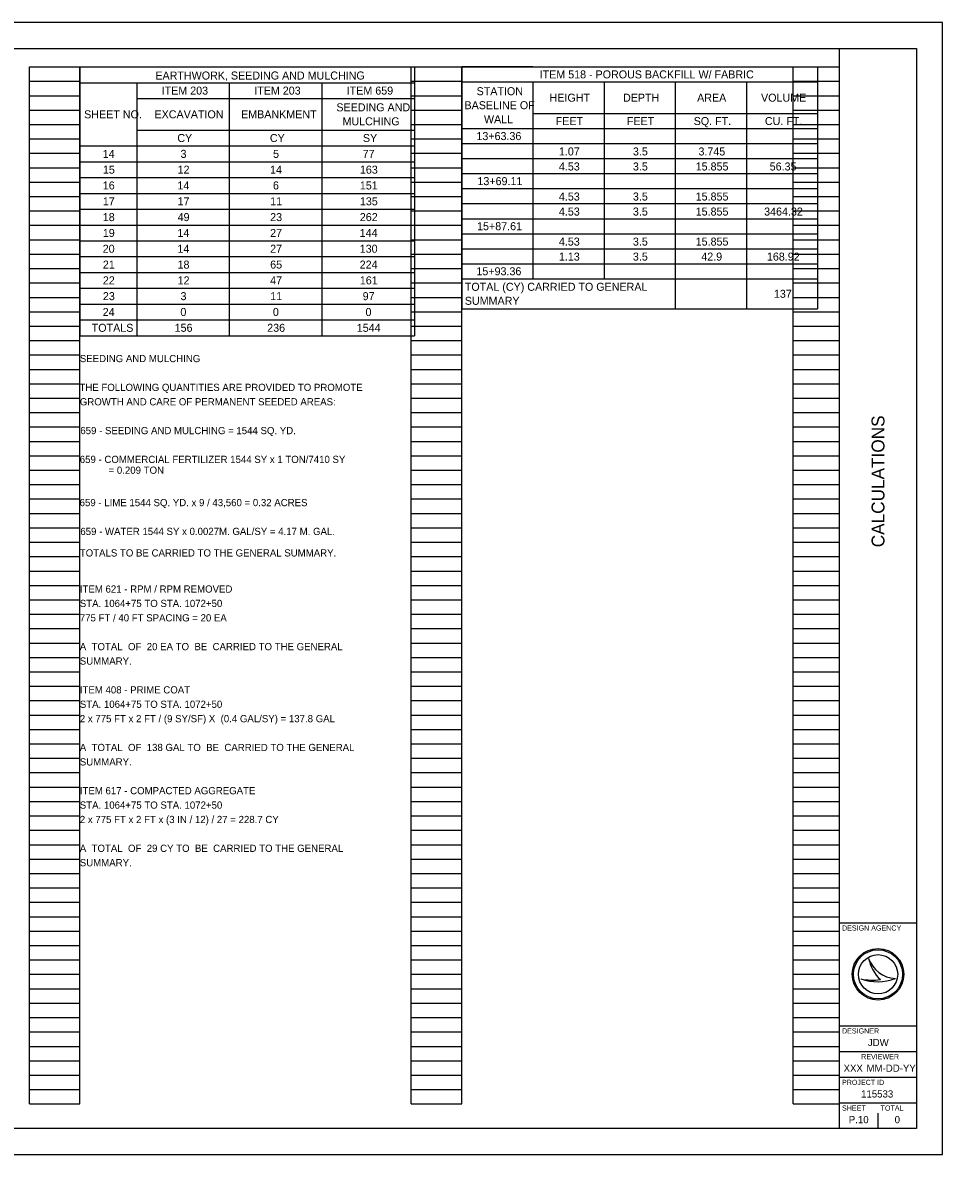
# Model space of a CAD drawing. Extents: x 0 to 34, y 0 to 22.
# Drawn here: x 16.13 to 34, y 0 to 22 of the extents above; entities that cross this region are included whole.
import ezdxf

# ---------------------------------------------------------------- set-up
doc = ezdxf.new("R2010")
doc.units = 0
for name, color, linetype in [('SH_Border', 7, 'Continuous'), ('SH_Cut_Line', 7, 'Continuous'), ('SH_Data', 7, 'Continuous'), ('SH_Text', 7, 'Continuous')]:
    doc.layers.add(name, color=color, linetype=linetype)

msp = doc.modelspace()

# ---------------------------------------------------------------- linework, layer by layer
at = {"layer": 'SH_Border'}
for p, q in [((32, 0.5), (32, 21.5)), ((32, 4.5), (33.5, 4.5)), ((32, 2.5), (33.5, 2.5)), ((32, 2), (33.5, 2)), ((32, 1.5), (33.5, 1.5)), ((32, 1), (33.5, 1))]:
    msp.add_line(p, q, dxfattribs=at)
msp.add_lwpolyline([(1.5, 21.5), (33.5, 21.5), (33.5, 0.5), (1.5, 0.5)], close=True, dxfattribs=at)
at = {"layer": 'SH_Cut_Line'}
msp.add_lwpolyline([(0, 0), (34, 0), (34, 22), (0, 22)], close=True, dxfattribs=at)
at = {"layer": 'SH_Data'}
for p, q in [((16.26, 0.98), (16.26, 21.14)), ((16.26, 21.14), (17.24, 21.14)), ((17.24, 0.98), (17.24, 21.14)), ((23.68, 0.98), (23.68, 21.14)), ((23.68, 21.14), (24.66, 21.14)), ((24.66, 0.98), (24.66, 21.14)), ((31.1, 0.98), (31.1, 21.14)), ((31.1, 21.14), (32, 21.14)), ((32, 0.98), (32, 21.14)), ((16.26, 20.86), (17.24, 20.86)), ((23.68, 20.86), (24.66, 20.86)), ((31.1, 20.86), (32, 20.86)), ((16.26, 20.58), (17.24, 20.58)), ((23.68, 20.58), (24.66, 20.58)), ((31.1, 20.58), (32, 20.58)), ((16.26, 20.3), (17.24, 20.3)), ((23.68, 20.3), (24.66, 20.3)), ((31.1, 20.3), (32, 20.3)), ((16.26, 20.02), (17.24, 20.02)), ((23.68, 20.02), (24.66, 20.02)), ((31.1, 20.02), (32, 20.02)), ((16.26, 19.74), (17.24, 19.74)), ((23.68, 19.74), (24.66, 19.74)), ((31.1, 19.74), (32, 19.74)), ((16.26, 19.46), (17.24, 19.46)), ((23.68, 19.46), (24.66, 19.46)), ((31.1, 19.46), (32, 19.46)), ((16.26, 19.18), (17.24, 19.18)), ((23.68, 19.18), (24.66, 19.18)), ((31.1, 19.18), (32, 19.18)), ((16.26, 18.9), (17.24, 18.9)), ((23.68, 18.9), (24.66, 18.9)), ((31.1, 18.9), (32, 18.9)), ((16.26, 18.62), (17.24, 18.62)), ((23.68, 18.62), (24.66, 18.62)), ((31.1, 18.62), (32, 18.62)), ((16.26, 18.34), (17.24, 18.34)), ((23.68, 18.34), (24.66, 18.34)), ((31.1, 18.34), (32, 18.34)), ((16.26, 18.06), (17.24, 18.06)), ((23.68, 18.06), (24.66, 18.06)), ((31.1, 18.06), (32, 18.06)), ((16.26, 17.78), (17.24, 17.78)), ((23.68, 17.78), (24.66, 17.78)), ((31.1, 17.78), (32, 17.78)), ((16.26, 17.5), (17.24, 17.5)), ((23.68, 17.5), (24.66, 17.5)), ((31.1, 17.5), (32, 17.5)), ((16.26, 17.22), (17.24, 17.22)), ((23.68, 17.22), (24.66, 17.22)), ((31.1, 17.22), (32, 17.22)), ((16.26, 16.94), (17.24, 16.94)), ((23.68, 16.94), (24.66, 16.94)), ((31.1, 16.94), (32, 16.94)), ((16.26, 16.66), (17.24, 16.66)), ((23.68, 16.66), (24.66, 16.66)), ((31.1, 16.66), (32, 16.66)), ((16.26, 16.38), (17.24, 16.38)), ((23.68, 16.38), (24.66, 16.38)), ((31.1, 16.38), (32, 16.38)), ((16.26, 16.1), (17.24, 16.1)), ((23.68, 16.1), (24.66, 16.1)), ((31.1, 16.1), (32, 16.1)), ((16.26, 15.82), (17.24, 15.82)), ((23.68, 15.82), (24.66, 15.82)), ((31.1, 15.82), (32, 15.82)), ((16.26, 15.54), (17.24, 15.54)), ((23.68, 15.54), (24.66, 15.54)), ((31.1, 15.54), (32, 15.54)), ((16.26, 15.26), (17.24, 15.26)), ((23.68, 15.26), (24.66, 15.26)), ((31.1, 15.26), (32, 15.26)), ((16.26, 14.98), (17.24, 14.98)), ((23.68, 14.98), (24.66, 14.98)), ((31.1, 14.98), (32, 14.98)), ((16.26, 14.7), (17.24, 14.7)), ((23.68, 14.7), (24.66, 14.7)), ((31.1, 14.7), (32, 14.7)), ((16.26, 14.42), (17.24, 14.42)), ((23.68, 14.42), (24.66, 14.42)), ((31.1, 14.42), (32, 14.42)), ((16.26, 14.14), (17.24, 14.14)), ((23.68, 14.14), (24.66, 14.14)), ((31.1, 14.14), (32, 14.14)), ((16.26, 13.86), (17.24, 13.86)), ((23.68, 13.86), (24.66, 13.86)), ((31.1, 13.86), (32, 13.86)), ((16.26, 13.58), (17.24, 13.58)), ((23.68, 13.58), (24.66, 13.58)), ((31.1, 13.58), (32, 13.58)), ((16.26, 13.3), (17.24, 13.3)), ((23.68, 13.3), (24.66, 13.3)), ((31.1, 13.3), (32, 13.3)), ((16.26, 13.02), (17.24, 13.02)), ((23.68, 13.02), (24.66, 13.02)), ((31.1, 13.02), (32, 13.02)), ((16.26, 12.74), (17.24, 12.74)), ((23.68, 12.74), (24.66, 12.74)), ((31.1, 12.74), (32, 12.74)), ((16.26, 12.46), (17.24, 12.46)), ((23.68, 12.46), (24.66, 12.46)), ((31.1, 12.46), (32, 12.46)), ((16.26, 12.18), (17.24, 12.18)), ((23.68, 12.18), (24.66, 12.18)), ((31.1, 12.18), (32, 12.18)), ((16.26, 11.9), (17.24, 11.9)), ((23.68, 11.9), (24.66, 11.9)), ((31.1, 11.9), (32, 11.9)), ((16.26, 11.62), (17.24, 11.62)), ((23.68, 11.62), (24.66, 11.62)), ((31.1, 11.62), (32, 11.62)), ((16.26, 11.34), (17.24, 11.34)), ((23.68, 11.34), (24.66, 11.34)), ((31.1, 11.34), (32, 11.34)), ((16.26, 11.06), (17.24, 11.06)), ((23.68, 11.06), (24.66, 11.06)), ((31.1, 11.06), (32, 11.06)), ((16.26, 10.78), (17.24, 10.78)), ((23.68, 10.78), (24.66, 10.78)), ((31.1, 10.78), (32, 10.78)), ((16.26, 10.5), (17.24, 10.5)), ((23.68, 10.5), (24.66, 10.5)), ((31.1, 10.5), (32, 10.5)), ((16.26, 10.22), (17.24, 10.22)), ((23.68, 10.22), (24.66, 10.22)), ((31.1, 10.22), (32, 10.22)), ((16.26, 9.94), (17.24, 9.94)), ((23.68, 9.94), (24.66, 9.94)), ((31.1, 9.94), (32, 9.94)), ((16.26, 9.66), (17.24, 9.66)), ((23.68, 9.66), (24.66, 9.66)), ((31.1, 9.66), (32, 9.66)), ((16.26, 9.38), (17.24, 9.38)), ((23.68, 9.38), (24.66, 9.38)), ((31.1, 9.38), (32, 9.38)), ((16.26, 9.1), (17.24, 9.1)), ((23.68, 9.1), (24.66, 9.1)), ((31.1, 9.1), (32, 9.1)), ((16.26, 8.82), (17.24, 8.82)), ((23.68, 8.82), (24.66, 8.82)), ((31.1, 8.82), (32, 8.82)), ((16.26, 8.54), (17.24, 8.54)), ((23.68, 8.54), (24.66, 8.54)), ((31.1, 8.54), (32, 8.54)), ((16.26, 8.26), (17.24, 8.26)), ((23.68, 8.26), (24.66, 8.26)), ((31.1, 8.26), (32, 8.26)), ((16.26, 7.98), (17.24, 7.98)), ((23.68, 7.98), (24.66, 7.98)), ((31.1, 7.98), (32, 7.98)), ((16.26, 7.7), (17.24, 7.7)), ((23.68, 7.7), (24.66, 7.7)), ((31.1, 7.7), (32, 7.7)), ((16.26, 7.42), (17.24, 7.42)), ((23.68, 7.42), (24.66, 7.42)), ((31.1, 7.42), (32, 7.42)), ((16.26, 7.14), (17.24, 7.14)), ((23.68, 7.14), (24.66, 7.14)), ((31.1, 7.14), (32, 7.14)), ((16.26, 6.86), (17.24, 6.86)), ((23.68, 6.86), (24.66, 6.86)), ((31.1, 6.86), (32, 6.86)), ((16.26, 6.58), (17.24, 6.58)), ((23.68, 6.58), (24.66, 6.58)), ((31.1, 6.58), (32, 6.58)), ((16.26, 6.3), (17.24, 6.3)), ((23.68, 6.3), (24.66, 6.3)), ((31.1, 6.3), (32, 6.3)), ((16.26, 6.02), (17.24, 6.02)), ((23.68, 6.02), (24.66, 6.02)), ((31.1, 6.02), (32, 6.02)), ((16.26, 5.74), (17.24, 5.74)), ((23.68, 5.74), (24.66, 5.74)), ((31.1, 5.74), (32, 5.74)), ((16.26, 5.46), (17.24, 5.46)), ((23.68, 5.46), (24.66, 5.46)), ((31.1, 5.46), (32, 5.46)), ((16.26, 5.18), (17.24, 5.18)), ((23.68, 5.18), (24.66, 5.18)), ((31.1, 5.18), (32, 5.18)), ((16.26, 4.9), (17.24, 4.9)), ((23.68, 4.9), (24.66, 4.9)), ((31.1, 4.9), (32, 4.9)), ((16.26, 4.62), (17.24, 4.62)), ((23.68, 4.62), (24.66, 4.62)), ((31.1, 4.62), (32, 4.62)), ((16.26, 4.34), (17.24, 4.34)), ((23.68, 4.34), (24.66, 4.34)), ((31.1, 4.34), (32, 4.34)), ((16.26, 4.06), (17.24, 4.06)), ((23.68, 4.06), (24.66, 4.06)), ((31.1, 4.06), (32, 4.06)), ((16.26, 3.78), (17.24, 3.78)), ((23.68, 3.78), (24.66, 3.78)), ((31.1, 3.78), (32, 3.78)), ((32.567, 3.81), (32.567, 3.81)), ((16.26, 3.5), (17.24, 3.5)), ((23.68, 3.5), (24.66, 3.5)), ((31.1, 3.5), (32, 3.5)), ((32.417, 3.41), (32.417, 3.41)), ((32.75, 3.5), (32.75, 3.5)), ((33.087, 3.419), (33.087, 3.419)), ((16.26, 3.22), (17.24, 3.22)), ((23.68, 3.22), (24.66, 3.22)), ((31.1, 3.22), (32, 3.22)), ((16.26, 2.94), (17.24, 2.94)), ((23.68, 2.94), (24.66, 2.94)), ((31.1, 2.94), (32, 2.94)), ((16.26, 2.66), (17.24, 2.66)), ((23.68, 2.66), (24.66, 2.66)), ((31.1, 2.66), (32, 2.66)), ((16.26, 2.38), (17.24, 2.38)), ((23.68, 2.38), (24.66, 2.38)), ((31.1, 2.38), (32, 2.38)), ((16.26, 2.1), (17.24, 2.1)), ((23.68, 2.1), (24.66, 2.1)), ((31.1, 2.1), (32, 2.1)), ((16.26, 1.82), (17.24, 1.82)), ((23.68, 1.82), (24.66, 1.82)), ((31.1, 1.82), (32, 1.82)), ((16.26, 1.54), (17.24, 1.54)), ((23.68, 1.54), (24.66, 1.54)), ((31.1, 1.54), (32, 1.54)), ((16.26, 1.26), (17.24, 1.26)), ((23.68, 1.26), (24.66, 1.26)), ((31.1, 1.26), (32, 1.26)), ((16.26, 0.98), (17.24, 0.98)), ((23.68, 0.98), (24.66, 0.98)), ((31.1, 0.98), (32, 0.98)), ((32.375, 0.675), (32.375, 0.675)), ((32.75, 0.5), (32.75, 0.8))]:
    msp.add_line(p, q, dxfattribs=at)
for radius in [0.5, 0.477, 0.477, 0.382]:
    msp.add_circle((32.75, 3.5), radius, dxfattribs=at)
for centre, radius, start, end in [((33.116, 3.998), 0.58, 198.9257, 198.9319), ((33.347, 3.97), 0.796, 191.6379, 191.6421), ((33.116, 3.998), 0.58, 198.9319, 267.1657), ((33.347, 3.97), 0.796, 191.6421, 226.0947), ((32.739, 4.37), 1.013, 251.4576, 290.0832), ((32.648, 4.654), 1.266, 259.4964, 259.4995), ((32.739, 4.37), 1.013, 251.4527, 251.4576), ((32.648, 4.654), 1.266, 259.4995, 276.6672)]:
    msp.add_arc(centre, radius, start, end, dxfattribs=at)
at = {"layer": 'SH_Text'}
for p, q in [((17.24, 21.14), (23.742, 21.14)), ((17.24, 21.14), (17.24, 15.914)), ((23.742, 21.14), (23.742, 15.914)), ((24.66, 21.14), (31.577, 21.14)), ((24.66, 21.14), (24.66, 16.436)), ((31.577, 21.14), (31.577, 16.436)), ((17.24, 20.833), (23.742, 20.833)), ((18.347, 20.833), (18.347, 15.914)), ((20.145, 20.833), (20.145, 15.914)), ((21.944, 20.833), (21.944, 15.914)), ((24.66, 20.848), (31.577, 20.848)), ((26.043, 20.848), (26.043, 17.021)), ((27.427, 20.848), (27.427, 17.021)), ((28.81, 20.848), (28.81, 16.436)), ((30.194, 20.848), (30.194, 16.436)), ((18.347, 20.525), (23.742, 20.525)), ((26.043, 20.233), (31.577, 20.233)), ((18.347, 19.91), (23.742, 19.91)), ((24.66, 19.941), (31.577, 19.941)), ((17.24, 19.603), (23.742, 19.603)), ((24.66, 19.649), (31.577, 19.649)), ((17.24, 19.295), (23.742, 19.295)), ((24.66, 19.357), (31.577, 19.357)), ((17.24, 18.988), (23.742, 18.988)), ((24.66, 19.065), (31.577, 19.065)), ((24.66, 18.773), (31.577, 18.773)), ((17.24, 18.681), (23.742, 18.681)), ((24.66, 18.481), (31.577, 18.481)), ((17.24, 18.373), (23.742, 18.373)), ((17.24, 18.066), (23.742, 18.066)), ((24.66, 18.189), (31.577, 18.189)), ((24.66, 17.897), (31.577, 17.897)), ((17.24, 17.758), (23.742, 17.758)), ((24.66, 17.605), (31.577, 17.605)), ((17.24, 17.451), (23.742, 17.451)), ((24.66, 17.313), (31.577, 17.313)), ((17.24, 17.144), (23.742, 17.144)), ((24.66, 17.021), (31.577, 17.021)), ((17.24, 16.836), (23.742, 16.836)), ((17.24, 16.529), (23.742, 16.529)), ((24.66, 16.436), (31.577, 16.436)), ((17.24, 16.221), (23.742, 16.221)), ((17.24, 15.914), (23.742, 15.914))]:
    msp.add_line(p, q, dxfattribs=at)
for points in [[(24.66, 21.14), (26.043, 21.14), (26.043, 21.14), (24.66, 21.14)], [(24.66, 21.14), (24.66, 21.14), (24.66, 21.14), (24.66, 21.14)], [(24.66, 21.14), (26.043, 21.14), (26.043, 21.14), (24.66, 21.14)], [(24.66, 21.14), (26.043, 21.14), (26.043, 21.14), (24.66, 21.14)], [(24.66, 21.14), (26.043, 21.14), (26.043, 21.14), (24.66, 21.14)], [(24.66, 21.14), (26.043, 21.14), (26.043, 21.14), (24.66, 21.14)], [(24.66, 21.14), (24.66, 21.14), (24.66, 20.525), (24.66, 20.525)], [(24.66, 21.14), (24.66, 21.14), (24.66, 20.848), (24.66, 20.848)], [(24.66, 21.14), (24.66, 21.14), (24.66, 20.848), (24.66, 20.848)], [(24.66, 21.14), (24.66, 21.14), (24.66, 20.848), (24.66, 20.848)], [(24.66, 21.14), (24.66, 21.14), (24.66, 20.848), (24.66, 20.848)], [(24.66, 21.14), (24.66, 21.14), (24.66, 20.848), (24.66, 20.848)], [(24.66, 21.14), (24.66, 21.14), (24.66, 20.848), (24.66, 20.848)], [(24.66, 21.14), (24.66, 21.14), (24.66, 20.848), (24.66, 20.848)], [(24.66, 21.14), (24.66, 21.14), (24.66, 20.848), (24.66, 20.848)], [(24.66, 21.14), (24.66, 21.14), (24.66, 20.848), (24.66, 20.848)], [(24.66, 21.14), (24.66, 21.14), (24.66, 20.848), (24.66, 20.848)], [(24.66, 21.14), (24.66, 21.14), (24.66, 20.848), (24.66, 20.848)]]:
    msp.add_lwpolyline(points, close=True, dxfattribs=at)

# ---------------------------------------------------------------- texts
at = {"layer": 'SH_Data'}
msp.add_text('CALCULATIONS', height=0.25, rotation=90, dxfattribs=at).set_placement((32.875, 11.801))
for s, height, p in [('DESIGN AGENCY', 0.1, (32.05, 4.35)), ('DESIGNER', 0.1, (32.05, 2.35)), ('JDW', 0.14, (32.553, 2.105)), ('REVIEWER', 0.1, (32.422, 1.85)), ('XXX', 0.14, (32.081, 1.605)), ('MM-DD-YY', 0.14, (32.527, 1.605)), ('PROJECT ID', 0.1, (32.05, 1.35)), ('115533', 0.14, (32.421, 1.105)), ('SHEET', 0.1, (32.05, 0.85)), ('TOTAL', 0.1, (32.8, 0.85)), ('P.10', 0.14, (32.182, 0.605)), ('0', 0.14, (33.073, 0.605))]:
    msp.add_text(s, height=height, dxfattribs=at).set_placement(p)
at = {"layer": 'SH_Text'}
for s, height, p in [('EARTHWORK, SEEDING AND MULCHING', 0.15556, (18.708, 20.894)), ('ITEM 518 - POROUS BACKFILL W/ FABRIC', 0.15556, (26.175, 20.916)), ('ITEM 203', 0.1556, (18.83, 20.601)), ('ITEM 203', 0.1556, (20.629, 20.601)), ('ITEM 659', 0.1556, (22.426, 20.601)), ('STATION ', 0.1556, (24.95, 20.589)), ('BASELINE OF ', 0.15556, (24.715, 20.317)), ('HEIGHT', 0.1556, (26.368, 20.463)), ('DEPTH', 0.1556, (27.795, 20.463)), ('AREA', 0.1556, (29.235, 20.463)), ('VOLUME', 0.1556, (30.477, 20.463)), ('SHEET NO.', 0.1556, (17.324, 20.14)), ('EXCAVATION', 0.1556, (18.691, 20.14)), ('EMBANKMENT', 0.1556, (20.373, 20.14)), ('SEEDING AND ', 0.15556, (22.225, 20.276)), ('MULCHING', 0.1556, (22.344, 20.004)), ('WALL', 0.1556, (25.093, 20.045)), ('FEET', 0.1556, (26.487, 20.009)), ('FEET', 0.1556, (27.87, 20.009)), ('SQ. FT.', 0.1556, (29.168, 20.009)), ('CU. FT.', 0.1556, (30.552, 20.009)), ('CY', 0.1556, (19.135, 19.679)), ('CY', 0.1556, (20.933, 19.679)), ('SY', 0.1556, (22.741, 19.679)), ('13+63.36', 0.1556, (24.946, 19.717)), ('14', 0.1556, (17.685, 19.371)), ('3', 0.156, (19.197, 19.371)), ('5', 0.156, (20.995, 19.371)), ('77', 0.1556, (22.736, 19.371)), ('1.07', 0.1556, (26.549, 19.418)), ('3.5', 0.1556, (27.987, 19.418)), ('3.745', 0.1556, (29.261, 19.418)), ('15', 0.1556, (17.688, 19.064)), ('12', 0.1556, (19.14, 19.064)), ('14', 0.1556, (20.936, 19.064)), ('163', 0.1556, (22.682, 19.064)), ('4.53', 0.1556, (26.549, 19.126)), ('3.5', 0.1556, (27.987, 19.126)), ('15.855', 0.1556, (29.207, 19.126)), ('56.35', 0.1556, (30.645, 19.126)), ('13+69.11', 0.1556, (24.966, 18.841)), ('16', 0.1556, (17.686, 18.757)), ('14', 0.1556, (19.137, 18.757)), ('6', 0.156, (20.993, 18.757)), ('151', 0.1556, (22.681, 18.757)), ('4.53', 0.1556, (26.549, 18.542)), ('3.5', 0.1556, (27.987, 18.542)), ('15.855', 0.1556, (29.207, 18.542)), ('17', 0.1556, (17.687, 18.449)), ('17', 0.1556, (19.139, 18.449)), ('11', 0.1556, (20.939, 18.449)), ('135', 0.1556, (22.682, 18.449)), ('18', 0.1556, (17.686, 18.142)), ('49', 0.1556, (19.14, 18.142)), ('23', 0.1556, (20.939, 18.142)), ('262', 0.1556, (22.681, 18.142)), ('4.53', 0.1556, (26.549, 18.25)), ('3.5', 0.1556, (27.987, 18.25)), ('15.855', 0.1556, (29.207, 18.25)), ('3464.32', 0.1556, (30.537, 18.25)), ('15+87.61', 0.1556, (24.959, 17.965)), ('19', 0.1556, (17.687, 17.834)), ('14', 0.1556, (19.137, 17.834)), ('27', 0.1556, (20.938, 17.834)), ('144', 0.1556, (22.678, 17.834)), ('4.53', 0.1556, (26.549, 17.666)), ('3.5', 0.1556, (27.987, 17.666)), ('15.855', 0.1556, (29.207, 17.666)), ('20', 0.1556, (17.685, 17.527)), ('14', 0.1556, (19.137, 17.527)), ('27', 0.1556, (20.938, 17.527)), ('130', 0.1556, (22.679, 17.527)), ('1.13', 0.1556, (26.549, 17.374)), ('3.5', 0.1556, (27.987, 17.374)), ('42.9', 0.1556, (29.316, 17.374)), ('168.92', 0.1556, (30.591, 17.374)), ('21', 0.1556, (17.688, 17.219)), ('18', 0.1556, (19.139, 17.219)), ('65', 0.1556, (20.939, 17.219)), ('224', 0.1556, (22.678, 17.219)), ('15+93.36', 0.1556, (24.946, 17.089)), ('22', 0.1556, (17.688, 16.912)), ('12', 0.1556, (19.14, 16.912)), ('47', 0.1556, (20.938, 16.912)), ('161', 0.1556, (22.681, 16.912)), ('TOTAL (CY) CARRIED TO GENERAL ', 0.15556, (24.721, 16.787)), ('23', 0.1556, (17.688, 16.605)), ('3', 0.156, (19.197, 16.605)), ('11', 0.1556, (20.939, 16.605)), ('97', 0.1556, (22.736, 16.605)), ('137', 0.1556, (30.727, 16.651)), ('SUMMARY', 0.1556, (24.721, 16.515)), ('24', 0.1556, (17.685, 16.297)), ('0', 0.156, (19.194, 16.297)), ('0', 0.156, (20.992, 16.297)), ('0', 0.156, (22.791, 16.297)), ('TOTALS', 0.1556, (17.471, 15.99)), ('156', 0.1556, (19.083, 15.99)), ('236', 0.1556, (20.881, 15.99)), ('1544', 0.1556, (22.622, 15.99)), ('SEEDING AND MULCHING', 0.14, (17.24, 15.4)), ('THE FOLLOWING QUANTITIES ARE PROVIDED TO PROMOTE', 0.14, (17.233, 14.84)), ('GROWTH AND CARE OF PERMANENT SEEDED AREAS:', 0.14, (17.24, 14.56)), ('659 - SEEDING AND MULCHING = 1544 SQ. YD.', 0.14, (17.25, 14)), ('659 - COMMERCIAL FERTILIZER 1544 SY x 1 TON/7410 SY ', 0.14, (17.239, 13.44)), ('= 0.209 TON', 0.14, (17.799, 13.23)), ('659 - LIME 1544 SQ. YD. x 9 / 43,560 = 0.32 ACRES', 0.14, (17.236, 12.6)), ('659 - WATER 1544 SY x 0.0027M. GAL/SY = 4.17 M. GAL.', 0.14, (17.25, 12.04)), ('TOTALS TO BE CARRIED TO THE GENERAL SUMMARY.', 0.14, (17.24, 11.622)), ('ITEM 621 - RPM / RPM REMOVED', 0.14, (17.24, 10.92)), ('STA. 1064+75 TO STA. 1072+50', 0.14, (17.24, 10.64)), ('775 FT / 40 FT SPACING = 20 EA', 0.14, (17.24, 10.36)), ('A  TOTAL  OF  20 EA TO  BE  CARRIED TO THE GENERAL', 0.14, (17.24, 9.8)), ('SUMMARY.', 0.14, (17.24, 9.52)), ('ITEM 408 - PRIME COAT', 0.14, (17.24, 8.96)), ('STA. 1064+75 TO STA. 1072+50', 0.14, (17.24, 8.68)), ('2 x 775 FT x 2 FT / (9 SY/SF) X  (0.4 GAL/SY) = 137.8 GAL', 0.14, (17.24, 8.4)), ('A  TOTAL  OF  138 GAL TO  BE  CARRIED TO THE GENERAL', 0.14, (17.24, 7.84)), ('SUMMARY.', 0.14, (17.24, 7.56)), ('ITEM 617 - COMPACTED AGGREGATE', 0.14, (17.24, 7)), ('STA. 1064+75 TO STA. 1072+50', 0.14, (17.24, 6.72)), ('2 x 775 FT x 2 FT x (3 IN / 12) / 27 = 228.7 CY', 0.14, (17.24, 6.44)), ('A  TOTAL  OF  29 CY TO  BE  CARRIED TO THE GENERAL', 0.14, (17.24, 5.88)), ('SUMMARY.', 0.14, (17.24, 5.6))]:
    msp.add_text(s, height=height, dxfattribs=at).set_placement(p)

doc.saveas('drawing.dxf')
